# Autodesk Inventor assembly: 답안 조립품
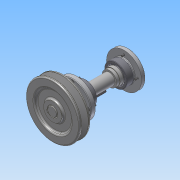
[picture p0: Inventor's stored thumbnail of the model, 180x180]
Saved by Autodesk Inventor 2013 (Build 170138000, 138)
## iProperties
Created: 2016-01
Part Number: 답안 조립품
Document SubType Name: Assembly
Designer: Administrator
Author: Administrator
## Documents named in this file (14)
- C:\Users\Administrator\Desktop\460106V1034\답안 조립품.iam
- C:\Users\Administrator\Desktop\460106V1034\답안 본체.ipt
- C:\Users\Administrator\Desktop\460106V1034\뒤커버.ipt
- C:\Users\Administrator\Desktop\460106V1034\볼트 M3 x 8.ipt
- C:\Users\Administrator\Desktop\460106V1034\베어링 6203.ipt
- C:\Users\Administrator\Desktop\460106V1034\앞커버.ipt
- C:\Users\Administrator\Desktop\460106V1034\볼트 M3 x 10.ipt
- C:\Users\Administrator\Desktop\460106V1034\오일씰 28 40 8.ipt
- C:\Users\Administrator\Desktop\460106V1034\축.ipt
- C:\Users\Administrator\Desktop\460106V1034\키 - 6 x 6 x 22.ipt
- C:\Users\Administrator\Desktop\460106V1034\키 - 5 x 5 x 18.ipt
- C:\Users\Administrator\Desktop\460106V1034\부시2.ipt
- C:\Users\Administrator\Desktop\460106V1034\부시1.ipt
- C:\Users\Administrator\Desktop\460106V1034\V-벨트풀리.ipt
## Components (9 placed, 3 different names)
1. V-벨트풀리:1 — 각도:3
2. ISO 4762 M3 x 8:1
3. ISO 4762 M3 x 8:2
4. ISO 4762 M3 x 8:3
5. ISO 4762 M3 x 8:4
6. ISO 4762 M3 x 10:1
7. ISO 4762 M3 x 10:2
8. ISO 4762 M3 x 10:3
9. ISO 4762 M3 x 10:4
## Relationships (1: Angle 1)
- 각도:3 [Angle]: V-벨트풀리:1
